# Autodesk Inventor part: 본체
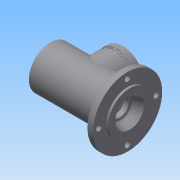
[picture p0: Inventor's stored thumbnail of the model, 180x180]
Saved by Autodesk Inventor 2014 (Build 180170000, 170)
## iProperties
Created: 2016-08
Part Number: 본체
Material: 일반
Document SubType Name: Modeling
Designer: 703-04
Density: 1 g/cm^3
Appearance: 기본값
Author: 703-04
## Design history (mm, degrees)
sketch "스케치1"
  geometry: C1 r 50 at (0, 0); 1 further point
  constraints: 1 centre point, 1 coincident
  dimensions: "d0" = 100 diameter of C1
extrude "돌출1" new body sketch "스케치1" distance "d1" = 10; taper "d2" = 0 deg
sketch "스케치2"
  geometry: C1 r 50 at (0, 0) reference; C2 r 31 at (0, 0)
  constraints: 1 centre point, 1 coincident
  dimensions: "d3" = 62 diameter of C2
extrude "돌출2" join sketch "스케치2" distance "d4" = 3; taper "d5" = 0 deg
sketch "스케치3" dims "d6" = 83
  geometry: L1 (0, 0)-(0, 41.5); C1 r 50 at (0, 0) reference; C2 r 4 at (0, 41.5)
  constraints: 2 coincident, 2 end point, 1 centre point, 1 vertical, 1 vertical alignment, 2 other
  dimensions: "d7" = 8 diameter of C2
extrude "돌출3" cut sketch "스케치3" stored distance "d9" = 3; taper "d10" = 0 deg
fillet "모깎기1" dims "d14" = 3
sketch "스케치4"
  geometry: C1 r 47 at (0, 0) reference; C2 r 31 at (0, 0)
  constraints: 1 centre point, 1 coincident
  dimensions: "d15" = 62 diameter of C2
extrude "돌출4" join sketch "스케치4" distance "d16" = 102; taper "d17" = 0 deg
sketch "스케치5"
  geometry: L1 (13, -31)-(13, 31) reference; L2 (13, 0)-(13, 21); L3 (13, 0)-(-1, 0); L4 (-1, 0)-(-1, 16); L5 (0, -47)-(0, 47) reference; L6 (-1, 16)-(13, 21); 1 further point
  constraints: 8 end point, 1 midpoint, 1 parallel, 1 perpendicular, 1 point on line
  dimensions: "d19" = 14 distance of L2.start L3.end; "d20" = 42 diameter of L2.end L3; "d21" = 32 diameter of L4.end L3
revolve "회전1" sketch "스케치5" stored, may be unused: angle "d22" = 90 deg
sketch "스케치6"
  geometry: C1 r 16 at (0, 0) reference; C2 r 12.5 at (0, 0)
  constraints: 1 centre point, 1 coincident
  dimensions: "d24" = 25 diameter of C2
extrude "돌출5" cut sketch "스케치6" distance "d25" = 7.3; taper "d26" = 0 deg
fillet "모깎기2" dims "d27" = 3
fillet "모깎기3" dims "d31" = 0.3
sketch "스케치7"
  geometry: C1 r 12.2 at (0, 0) reference; C2 r 10 at (0, 0)
  constraints: 1 centre point, 1 coincident
  dimensions: "d32" = 20 diameter of C2
extrude "돌출6" cut sketch "스케치7" distance "d33" = 2.7; taper "d34" = 0 deg
sketch "스케치8"
  geometry: C1 r 31 at (0, 0) reference
hole "구멍1" sketch "스케치8" at (0, 0) diameter "d35" = 40.376; stored, may be unused: countersink angle "d39" = 90 deg, drill point angle "d41" = 0 deg; dims "d36" = 6, "d37" = 4, "d38" = 2, "d40" = 9
chamfer "모따기2" distance "d44" = 0.7; stored, may be unused: second distance "d45" = 2, angle "d46" = 30 deg
sketch "스케치11"
  geometry: L1 (-93, 20.188)-(-93, -20.188) reference; L2 (-93, 0)-(-11, 0); L3 (-11, 10)-(-11, -10) reference; L4 (-11, 0)-(-11, 16.5); L5 (-11, 16.5)-(-16, 16.5); L6 (-16, 16.5)-(-16, 17.5); L7 (-93, 0)-(-93, 24); L8 (-93, 24)-(-90, 24); L9 (-90, 24)-(-90, 20); L10 (-90, 20)-(-81, 20); L11 (-102, -20.188)-(-102, 20.188) reference; L12 (-81, 20)-(-81, 17.5); L13 (-81, 17.5)-(-77.75, 17.5); L14 (-77.75, 17.5)-(-77.75, 18.5); L15 (-77.75, 18.5)-(-76, 18.5); L16 (-76, 18.5)-(-76, 17.5); L17 (0, 31)-(-102, 31) reference; L18 (-65, 26)-(-27, 26); L19 (-65, 26)-(-65, 17.5); L20 (-27, 26)-(-27, 17.5); L21 (-76, 17.5)-(-65, 17.5); L22 (-27, 17.5)-(-16, 17.5); 1 further point
  constraints: 36 end point, 10 perpendicular, 4 parallel, 2 midpoint, 1 point on line
  dimensions: "d47" = 33 diameter of L4.end L2; "d48" = 5 distance of L4.end L5.end; "d54" = 35 diameter of L6.end L2; "d55" = 48 diameter of L7.end L2; "d56" = 3 distance of L7.end L8.end; "d57" = 40 diameter of L9.end L2; "d58" = 21 distance from line of L10.end L11; "d59" = 35 diameter of L12.end L2; "d60" = 1.75 distance of L14.end L15.end; "d61" = 35 diameter of L16.end L2; "d62" = 37 diameter of L15 L2; "d63" = 26 distance from line of L11 L16.end; "d65" = 38 distance of L18.start L18.end; "d67" = 8.5 distance of L18.start L19.end; "d110" = 52 diameter of L18 L2; "d111" = 37.48333 distance of point (0, 0) L18.end
revolve "회전2" sketch "스케치11" stored, may be unused: angle "d69" = 90 deg
fillet "모깎기4" dims "d70" = 3
fillet "모깎기5" dims "d71" = 0.3
chamfer "모따기3" distance "d72" = 1; stored, may be unused: second distance "d73" = 2, angle "d74" = 30 deg
node "작업 평면1"
sketch "스케치12"
  geometry: L1 (102, -21.188)-(102, 21.188) reference; L2 (102, 0)-(46, 0); C1 r 30 at (46, 0); 1 further point
  constraints: 2 end point, 1 centre point, 1 coincident, 1 midpoint, 1 perpendicular
  dimensions: "d77" = 56 distance of L2.start L2.end; "d78" = 60 diameter of C1
extrude "돌출7" join sketch "스케치12" stored distance "d79" = 3; taper "d80" = 0 deg
sketch "스케치13"
  geometry: C1 r 30 at (0, 0) reference; C2 r 19 at (0, 0); 1 further point
  constraints: 1 centre point, 1 coincident
  dimensions: "d81" = 38 diameter of C2
extrude "돌출8" cut sketch "스케치13" stored distance "d82" = 3; taper "d83" = 0 deg
sketch "스케치15" dims "d84" = 48
  geometry: L1 (0, 0)-(0, 24); C1 r 30 at (0, 0) reference; 1 further point
  constraints: 2 end point, 1 coincident, 1 vertical, 1 vertical alignment, 2 other
hole "구멍2" sketch "스케치15" at (0, 24) diameter "d85" = 3.242; stored, may be unused: countersink angle "d89" = 90 deg, drill point angle "d91" = 118 deg; dims "d86" = 8, "d87" = 4, "d88" = 2, "d90" = 10
chamfer "모따기4" distance "d95" = 1; stored, may be unused: second distance "d96" = 2, angle "d97" = 30 deg
fillet "모깎기7" dims "d99" = 3
node "작업 평면2"
sketch "스케치17"
  geometry: L1 (-30, 0)-(30, 0) reference; L2 (0, 0)-(0, -10); L3 (1.621, -10)-(-1.621, -10) reference; 2 further points
  constraints: 2 coincident, 2 end point, 2 midpoint, 1 other
  dimensions: "d102" = 10 distance of L2.start L2.end (derived)
feature "엠보싱1" sketch "스케치17" dims "d103" = 0.5, "d104" = 0
fillet "모깎기9" dims "d106" = 3
node "솔리드1"
pattern_circular "원형 패턴1" dims angle "d12" = 360 deg
pattern_circular "원형 패턴2" dims angle "d93" = 360 deg
other parameters: "d75" = 49
